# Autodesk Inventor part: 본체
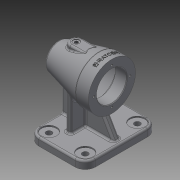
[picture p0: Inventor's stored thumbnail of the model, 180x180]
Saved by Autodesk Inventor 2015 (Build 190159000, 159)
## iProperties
Created: 2024-12
Part Number: 본체
Material: 일반
Document SubType Name: Modeling
Designer: 102-5
Density: 1 g/cm^3
Appearance: 기본값
Author: 102-5
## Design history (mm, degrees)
sketch "스케치1"
  geometry: C1 r 37 at (0, 0); 1 further point
  constraints: 1 centre point, 1 coincident
  dimensions: "d0" = 74 diameter of C1
extrude "돌출1" new body sketch "스케치1" distance "d1" = 20; taper "d2" = 0 deg
node "작업 평면1"
sketch "스케치2"
  geometry: C1 r 37 at (0, 0) reference
sketch "스케치3"
  geometry: C1 r 21 at (0, 0); 1 further point
  constraints: 1 centre point, 1 coincident
  dimensions: "d4" = 42 diameter of C1
feature "로프트1" sketch "스케치3" dims "d5" = 0, "d6" = 90 deg, "d7" = 0, "d8" = 90 deg
  node "모서리1"
node "작업 평면2"
sketch "스케치4"
  geometry: L1 (-74, -57)-(15, -57); L2 (15, -57)-(15, 57); L3 (15, 57)-(-74, 57); L4 (-74, 57)-(-74, -57); L5 (0, 37)-(0, -37) reference; 3 further points
  constraints: 8 end point, 2 midpoint, 2 parallel, 1 horizontal, 1 horizontal alignment, 1 perpendicular
  dimensions: "d10" = 15 distance from line of L2.end L5; "d11" = 114 distance between parallel lines of L3 L1; "d12" = 89 distance between parallel lines of L2 L4
extrude "돌출2" join sketch "스케치4" distance "d13" = 12; taper "d14" = 0 deg
sketch "스케치5"
  geometry: L1 (15, -57)-(15, 57) reference; L2 (-74, 57)-(-74, -57) reference; L3 (8, -5)-(-74, -5); L4 (-74, -5)-(-74, 5); L5 (-74, 5)-(8, 5); L6 (8, 5)-(8, -5); L7 (8, -5)-(-74, 5); L8 (-74, -5)-(8, 5); L9 (-37, -28)-(-45, -28); L10 (-45, -28)-(-45, 28); L11 (-45, 28)-(-37, 28); L12 (-37, 28)-(-37, -28); L13 (-37, -28)-(-45, 28); L14 (-45, -28)-(-37, 28); 5 further points
  constraints: 24 end point, 6 midpoint, 4 parallel, 2 horizontal, 2 horizontal alignment, 2 perpendicular, 1 point on line
  dimensions: "d15" = 10 distance between parallel lines of L5 L3; "d16" = 8 distance between parallel lines of L12 L10; "d17" = 29 distance between parallel lines of L10 L2; "d18" = 56 distance between parallel lines of L11 L9; "d19" = 7 distance between parallel lines of L1 L6
extrude "돌출3" join sketch "스케치5" distance "d20" = 70; taper "d21" = 0 deg
feature "면 기울기1" dims angle "d22" = 30 deg
fillet "모깎기1" dims "d23" = 16
sketch "스케치7"
  geometry: A1 r 16 centre (-1, -41) between (-1, -57) and (15, -41) reference; 1 further point
hole "구멍1" sketch "스케치7" at (-1, -41) diameter "d24" = 9; stored, may be unused: countersink angle "d28" = 90 deg, drill point angle "d30" = 118 deg; dims "d25" = 6, "d26" = 24, "d27" = 2, "d29" = 8
sketch "스케치8"
  geometry: A1 r 16 centre (-58, -41) between (-74, -41) and (-58, -57) reference; 1 further point
hole "구멍2" sketch "스케치8" at (-58, -41) diameter "d31" = 9; stored, may be unused: countersink angle "d35" = 90 deg, drill point angle "d37" = 118 deg; dims "d32" = 6, "d33" = 24, "d34" = 2, "d36" = 8
sketch "스케치10"
  geometry: L1 (20, 37)-(84, 21) reference; L2 (18, 32.346)-(63, 21.096); L3 (18, 32.346)-(18, 0); L4 (18, 0)-(63, 0); L5 (0, -37)-(0, 37) reference; L6 (63, 21.096)-(63, 0); 2 further points
  constraints: 8 end point, 2 vertical, 1 horizontal alignment, 1 midpoint, 1 parallel, 1 perpendicular
  dimensions: "d38" = 5 distance between parallel lines of L1 L2; "d39" = 18 distance between parallel lines of L3 L5; "d41" = 45 distance between parallel lines of L6 L3
revolve "회전1" sketch "스케치10" stored, may be unused: angle "d42" = 90 deg
sketch "스케치11"
  geometry: C1 r 37 at (0, 0) reference; C2 r 23.5 at (0, 0)
  constraints: 1 centre point, 1 coincident
  dimensions: "d43" = 47 diameter of C2
extrude "돌출4" cut sketch "스케치11" distance "d44" = 18; taper "d45" = 0 deg
sketch "스케치12"
  geometry: C1 r 21.096 at (0, 0) reference; C2 r 17.5 at (0, 0)
  constraints: 1 centre point, 1 coincident
  dimensions: "d46" = 35 diameter of C2
extrude "돌출5" cut sketch "스케치12" distance "d47" = 10; taper "d48" = 0 deg
sketch "스케치13"
  geometry: C1 r 17.5 at (0, 0) reference; C2 r 15.5 at (0, 0)
  constraints: 1 centre point, 1 coincident
  dimensions: "d49" = 31 diameter of C2
extrude "돌출6" cut sketch "스케치13" distance "d50" = 3; taper "d51" = 0 deg
sketch "스케치14"
  geometry: L1 (0, 0)-(-28.5, 0); C1 r 37 at (0, 0) reference
  constraints: 2 end point, 1 horizontal
  dimensions: "d52" = 28.5 distance of L1.start L1.end
hole "구멍3" sketch "스케치14" at (-28.5, 0) diameter "d53" = 3.242; stored, may be unused: countersink angle "d57" = 90 deg, drill point angle "d59" = 118 deg; dims "d54" = 8, "d55" = 24, "d56" = 2, "d58" = 10
node "작업 평면3"
sketch "스케치15"
  geometry: L1 (56, 0)-(26, 0); L2 (56, -10)-(26, -10); L3 (26, 10)-(56, 10); L4 (0, -37)-(0, 37) reference; A1 r 10 centre (56, 0) between (56, -10) and (56, 10); A2 r 10 centre (26, 0) between (26, 10) and (26, -10); 2 further points
  constraints: 8 end point, 4 point on circle, 4 tangent, 2 centre point, 2 horizontal alignment, 1 horizontal, 1 midpoint, 1 parallel
  dimensions: "d64" = 56 distance from line of L4 L1.start; "d65" = 20 distance between parallel lines of L2 L3; "d66" = 30 distance of L1.start L1.end
extrude "돌출7" join sketch "스케치15" distance "d67" = 30; taper "d68" = 0 deg
sketch "스케치16"
  geometry: L1 (0, 0)-(73, 0); L2 (63, -17.5)-(63, 15.977) reference; L3 (63, 19.851)-(63, -21.096) reference; L4 (63, -21.096)-(18, -32.346) reference; L5 (18, 31.785)-(18, -32.346) reference; L6 (0, -23.5)-(18, -23.5) reference; L7 (0, -23.5)-(0, 23.5) reference; L8 (63, -17.5)-(73, -17.5) reference; L9 (73, -15.5)-(73, 15.5) reference; L10 (73, -17.5)-(73, 17.5) reference
  constraints: 2 end point, 1 horizontal, 1 midpoint
revolve "회전2" sketch "스케치16" stored, may be unused: angle "d69" = 90 deg
sketch "스케치17"
  geometry: A1 r 10 centre (-56, 0) between (-56, 10) and (-56, -10) reference; 1 further point
hole "구멍4" sketch "스케치17" at (-56, 0) diameter "d70" = 5.188; stored, may be unused: countersink angle "d74" = 90 deg, drill point angle "d76" = 118 deg; dims "d71" = 12, "d72" = 10, "d73" = 1, "d75" = 16
fillet "모깎기2" dims "d77" = 5
fillet "모깎기3" dims "d78" = 3
fillet "모깎기4" dims "d79" = 0.3
chamfer "모따기1" distance "d80" = 1; stored, may be unused: second distance "d81" = 2, angle "d82" = 45 deg
fillet "모깎기5" dims "d83" = 3
fillet "모깎기6" dims "d84" = 3
fillet "모깎기7" dims "d85" = 3
fillet "모깎기8" dims "d86" = 3
fillet "모깎기9" dims "d87" = 3
node "작업 평면4"
sketch "스케치18"
  geometry: L1 (0, 37)-(0, -37) reference; 3 further points
  constraints: 1 horizontal alignment, 1 midpoint, 1 other
  dimensions: "d89" = 9 distance from line of point (-9, 0) L1
feature "엠보싱1" sketch "스케치18" dims "d0" = 74, "d90" = 0.5, "d91" = 0
node "솔리드1"
mirror "대칭1"
mirror "대칭2"
pattern_circular "원형 패턴1" dims angle "d61" = 360 deg
other parameters: "d3" = 64, "d9" = -82, "d40" = 45, "d63" = -115, "d88" = 148.75
